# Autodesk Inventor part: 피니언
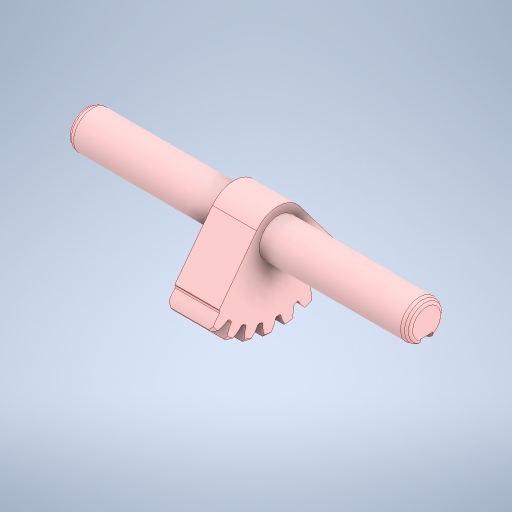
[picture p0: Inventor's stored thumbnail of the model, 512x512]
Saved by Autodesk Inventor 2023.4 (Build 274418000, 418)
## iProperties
Created: 2024-05
Part Number: 피니언
Material: 강철, 탄소
Document SubType Name: Modeling
Designer: user
Density: 7.85 g/cm^3
Appearance: 기본값
Author: jhkim
Sending System: Autodesk Inventor 2025
Preprocessor: ST-DEVELOPER v20
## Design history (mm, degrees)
feature "솔리드1"
node "솔리드2"
